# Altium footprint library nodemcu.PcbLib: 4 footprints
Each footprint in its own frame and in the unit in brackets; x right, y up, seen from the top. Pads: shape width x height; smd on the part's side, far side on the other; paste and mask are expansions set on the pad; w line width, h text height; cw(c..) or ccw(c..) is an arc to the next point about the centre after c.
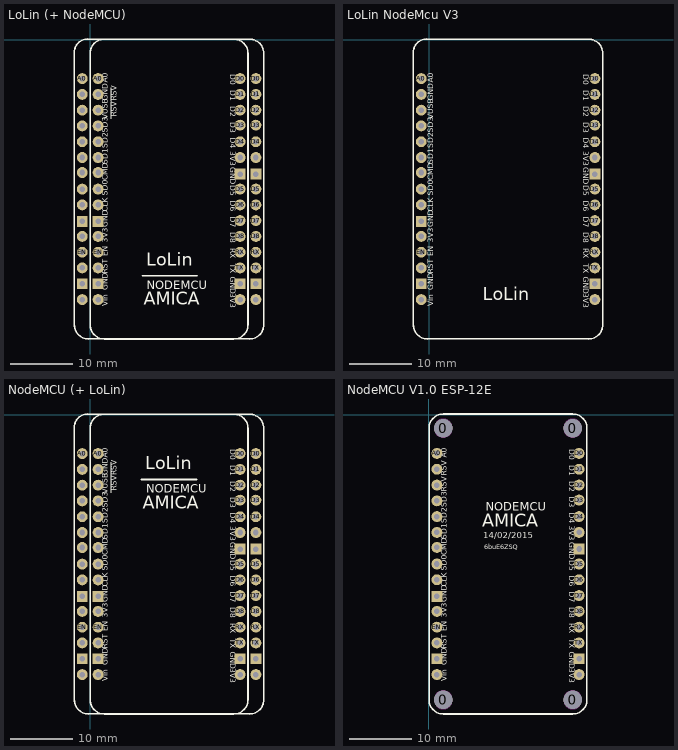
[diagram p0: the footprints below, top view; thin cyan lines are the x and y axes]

## LoLin (+ NodeMCU) [mil]
pads (60):
  round 69 hole 35: 3V3(-49,-1246) 3V3(51,-1246) 3V3(951,-1646) 3V3(951,-746) 3V3(1051,-1646) 3V3(1051,-746) A0(-49,-246) A0(51,-246) CLK(-49,-1046) CLK(51,-1046) CMD(-49,-841) CMD(51,-841) D0(951,-246) D0(1051,-246) D1(951,-346) D1(1051,-346) D2(951,-446) D2(1051,-446) D3(951,-541) D3(1051,-541) D4(951,-646) D4(1051,-646) D5(951,-946) D5(1051,-946) D6(951,-1046) D6(1051,-1046) D7(951,-1146) D7(1051,-1146) D8(951,-1246) D8(1051,-1246) EN(-49,-1346) EN(51,-1346) GND(-49,-346) RST(-49,-1446) RST(51,-1446) RX(951,-1346) RX(1051,-1346) SD0(-49,-946) SD0(51,-946) SD1(-49,-746) SD1(51,-746) SD2(-49,-646) SD2(51,-646) SD3(-49,-546) SD3(51,-546) TX(951,-1446) TX(1051,-1446) VIN(-49,-1646) VIN(51,-1646) VUSB(-49,-446) ""(51,-446) ""(51,-346)
  rect 69x69 hole 35: GND(-49,-1546) GND(-49,-1151) GND(51,-1546) GND(51,-1151) GND(951,-1546) GND(951,-851) GND(1051,-1546) GND(1051,-851)
Top Overlay:
  lines w3: 135,-500 135,-395 ; 135,-390 135,-305
  lines w10: -100,-1810 -100,-80 cw(c-15.07,-80) -15.07,4.93 ; -99,-1806 ccw(c-9,-1806) -9,-1896 1010,-1895 ; -14,4 1010,4 ; 330,-1495 680,-1495 ; 1011,-1896 ccw(c1011,-1806) 1101,-1806 1101,-86 ccw(c1011,-86) 1011,4 ; 1,-1806 ccw(c91,-1806) 91,-1896 911,-1896 ccw(c911,-1806) 1001,-1806 1001,-86 ccw(c911,-86) 911,4 91,4 ccw(c91,-86) 1,-86 1,-1806
  text "RSV" at 181,-487.43 h60
  text "RSV" at 181,-387 h60
  text "GND" at 126,-1188 h60
  text "3V3" at 126,-1285 h60
  text "EN" at 126,-1372 h60
  text "RST" at 126,-1484 h60
  text "GND" at 126,-1587 h60
  text "Vin" at 126,-1687 h60
  text "D7" at 876,-1121.23 h60
  text "D8" at 876,-1221.11 h60
  text "RX" at 876,-1320.06 h60
  text "TX" at 876,-1419 h60
  text "GND" at 876,-1502.2 h60
  text "3V3" at 876,-1606 h60
  text "D6" at 876,-1020.12 h60
  text "CMD" at 126,-889.14 h60
  text "D0" at 876,-220 h60
  text "D1" at 876,-321.35 h60
  text "D2" at 876,-421.58 h60
  text "D3" at 876,-521.58 h60
  text "D4" at 876,-620 h60
  text "3V3" at 876,-705.01 h60
  text "GND" at 876,-807 h60
  text "D5" at 876,-921 h60
  text "A0" at 126,-273 h60
  text "GND" at 126,-387 h60
  text "VUSB" at 125,-505 h60
  text "SD3" at 126,-587.86 h60
  text "SD2" at 126,-688.29 h60
  text "SD1" at 126,-788.71 h60
  text "SD0" at 126,-989.57 h60
  text "CLK" at 126,-1090 h60
  text "NODEMCU" at 360,-1599 h90
  text "AMICA" at 339,-1709 h140
  text "LoLin" at 355,-1460 h140

## LoLin NodeMcu V3 [mil]
pads (30):
  round 69 hole 35: 3V3(-49,-1246) 3V3(1051,-1646) 3V3(1051,-746) A0(-49,-246) CLK(-49,-1046) CMD(-49,-841) D0(1051,-246) D1(1051,-346) D2(1051,-446) D3(1051,-541) D4(1051,-646) D5(1051,-946) D6(1051,-1046) D7(1051,-1146) D8(1051,-1246) EN(-49,-1346) GND(-49,-346) RST(-49,-1446) RX(1051,-1346) SD0(-49,-946) SD1(-49,-746) SD2(-49,-646) SD3(-49,-546) TX(1051,-1446) VIN(-49,-1646) VUSB(-49,-446)
  rect 69x69 hole 35: GND(-49,-1546) GND(-49,-1151) GND(1051,-1546) GND(1051,-851)
Top Overlay:
  lines w10: -100,-1810 -100,-80 cw(c-15.07,-80) -15.07,4.93 ; -99,-1806 ccw(c-9,-1806) -9,-1896 1010,-1895 ; -14,4 1010,4 ; 1011,-1896 ccw(c1011,-1806) 1101,-1806 1101,-86 ccw(c1011,-86) 1011,4
  text "GND" at 41,-1188 h60
  text "3V3" at 41,-1285 h60
  text "EN" at 41,-1372 h60
  text "RST" at 41,-1484 h60
  text "GND" at 41,-1587 h60
  text "Vin" at 41,-1687 h60
  text "D7" at 966,-1121.23 h60
  text "D8" at 966,-1221.11 h60
  text "RX" at 966,-1320.06 h60
  text "TX" at 966,-1419 h60
  text "GND" at 966,-1502.2 h60
  text "3V3" at 966,-1606 h60
  text "D6" at 966,-1020.12 h60
  text "CMD" at 41,-889.14 h60
  text "D0" at 966,-220 h60
  text "D1" at 966,-321.35 h60
  text "D2" at 966,-421.58 h60
  text "D3" at 966,-521.58 h60
  text "D4" at 966,-620 h60
  text "3V3" at 966,-705.01 h60
  text "GND" at 966,-807 h60
  text "D5" at 966,-921 h60
  text "A0" at 41,-273 h60
  text "GND" at 41,-387 h60
  text "VUSB" at 40,-505 h60
  text "SD3" at 41,-587.86 h60
  text "SD2" at 41,-688.29 h60
  text "SD1" at 41,-788.71 h60
  text "SD0" at 41,-989.57 h60
  text "CLK" at 41,-1090 h60
  text "LoLin" at 340,-1680 h140

## NodeMCU (+ LoLin) [mil]
pads (60):
  round 69 hole 35: 3V3(-49,-1246) 3V3(51,-1246) 3V3(951,-1646) 3V3(951,-746) 3V3(1051,-1646) 3V3(1051,-746) A0(-49,-246) A0(51,-246) CLK(-49,-1046) CLK(51,-1046) CMD(-49,-841) CMD(51,-841) D0(951,-246) D0(1051,-246) D1(951,-346) D1(1051,-346) D2(951,-446) D2(1051,-446) D3(951,-541) D3(1051,-541) D4(951,-646) D4(1051,-646) D5(951,-946) D5(1051,-946) D6(951,-1046) D6(1051,-1046) D7(951,-1146) D7(1051,-1146) D8(951,-1246) D8(1051,-1246) EN(-49,-1346) EN(51,-1346) RST(-49,-1446) RST(51,-1446) RSV(51,-446) RSV(51,-346) RX(951,-1346) RX(1051,-1346) SD0(-49,-946) SD0(51,-946) SD1(-49,-746) SD1(51,-746) SD2(-49,-646) SD2(51,-646) SD3(-49,-546) SD3(51,-546) TX(951,-1446) TX(1051,-1446) VIN(-49,-1646) VIN(51,-1646) ""(-49,-446) ""(-49,-346)
  rect 69x69 hole 35: GND(-49,-1546) GND(-49,-1151) GND(51,-1546) GND(51,-1151) GND(951,-1546) GND(951,-851) GND(1051,-1546) GND(1051,-851)
Top Overlay:
  lines w3: 135,-495 135,-390 ; 135,-385 135,-300
  lines w10: -100,-1810 -100,-80 cw(c-15.07,-80) -15.07,4.93 ; -99,-1806 ccw(c-9,-1806) -9,-1896 1010,-1895 ; -14,4 1010,4 ; 325,-410 675,-410 ; 1011,-1896 ccw(c1011,-1806) 1101,-1806 1101,-86 ccw(c1011,-86) 1011,4 ; 1,-1806 ccw(c91,-1806) 91,-1896 911,-1896 ccw(c911,-1806) 1001,-1806 1001,-86 ccw(c911,-86) 911,4 91,4 ccw(c91,-86) 1,-86 1,-1806
  text "RSV" at 181,-482.43 h60
  text "RSV" at 181,-382 h60
  text "GND" at 126,-382 h60
  text "VUSB" at 125,-500 h60
  text "GND" at 126,-1188 h60
  text "3V3" at 126,-1285 h60
  text "EN" at 126,-1372 h60
  text "RST" at 126,-1484 h60
  text "GND" at 126,-1587 h60
  text "Vin" at 126,-1687 h60
  text "D7" at 876,-1121.23 h60
  text "D8" at 876,-1221.11 h60
  text "RX" at 876,-1320.06 h60
  text "TX" at 876,-1419 h60
  text "GND" at 876,-1502.2 h60
  text "3V3" at 876,-1606 h60
  text "D6" at 876,-1020.12 h60
  text "CMD" at 126,-889.14 h60
  text "D0" at 876,-220 h60
  text "D1" at 876,-321.35 h60
  text "D2" at 876,-421.58 h60
  text "D3" at 876,-521.58 h60
  text "D4" at 876,-620 h60
  text "3V3" at 876,-705.01 h60
  text "GND" at 876,-807 h60
  text "D5" at 876,-921 h60
  text "A0" at 126,-273 h60
  text "SD3" at 126,-587.86 h60
  text "SD2" at 126,-688.29 h60
  text "SD1" at 126,-788.71 h60
  text "SD0" at 126,-989.57 h60
  text "CLK" at 126,-1090 h60
  text "NODEMCU" at 355,-514 h90
  text "AMICA" at 334,-624 h140
  text "LoLin" at 350,-375 h140

## NodeMCU V1.0 ESP-12E [mil]
pads (34):
  round 115 hole 115 unplated paste-300 mask-300: 0(91,-1806) 0(91,-86) 0(911,-1806) 0(911,-86)
  round 69 hole 35: 3V3(51,-1246) 3V3(951,-1646) 3V3(951,-746) A0(51,-246) CLK(51,-1046) CMD(51,-841) D0(951,-246) D1(951,-346) D2(951,-446) D3(951,-541) D4(951,-646) D5(951,-946) D6(951,-1046) D7(951,-1146) D8(951,-1246) EN(51,-1346) RST(51,-1446) RSV(51,-446) RSV(51,-346) RX(951,-1346) SD0(51,-946) SD1(51,-746) SD2(51,-646) SD3(51,-546) TX(951,-1446) VIN(51,-1646)
  rect 69x69 hole 35: GND(51,-1546) GND(51,-1151) GND(951,-1546) GND(951,-851)
Top Overlay:
  lines w10: 1,-1806 ccw(c91,-1806) 91,-1896 911,-1896 ccw(c911,-1806) 1001,-1806 1001,-86 ccw(c911,-86) 911,4 91,4 ccw(c91,-86) 1,-86 1,-1806
  text "GND" at 126,-1188 h60
  text "3V3" at 126,-1285 h60
  text "EN" at 126,-1372 h60
  text "RST" at 126,-1484 h60
  text "GND" at 126,-1587 h60
  text "Vin" at 126,-1687 h60
  text "D7" at 876,-1121.23 h60
  text "D8" at 876,-1221.11 h60
  text "RX" at 876,-1320.06 h60
  text "TX" at 876,-1419 h60
  text "GND" at 876,-1502.2 h60
  text "3V3" at 876,-1606 h60
  text "D6" at 876,-1020.12 h60
  text "CMD" at 126,-889.14 h60
  text "D0" at 876,-220 h60
  text "D1" at 876,-321.35 h60
  text "D2" at 876,-421.58 h60
  text "D3" at 876,-521.58 h60
  text "D4" at 876,-620 h60
  text "3V3" at 876,-705.01 h60
  text "GND" at 876,-807 h60
  text "D5" at 876,-921 h60
  text "A0" at 126,-273 h60
  text "RSV" at 126,-387 h60
  text "RSV" at 126,-487.43 h60
  text "SD3" at 126,-587.86 h60
  text "SD2" at 126,-688.29 h60
  text "SD1" at 126,-788.71 h60
  text "SD0" at 126,-989.57 h60
  text "CLK" at 126,-1090 h60
  text "6buE6ZSQ" at 349,-853 h30
  text "NODEMCU" at 360,-629 h90
  text "AMICA" at 339,-739 h140
  text "14/02/2015" at 345,-798 h69
Keep-Out Layer:
  circle w2: c91,-86 r57.5
  circle w2: c911,-86 r57.5
  circle w2: c91,-1806 r57.5
  circle w2: c911,-1806 r57.5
